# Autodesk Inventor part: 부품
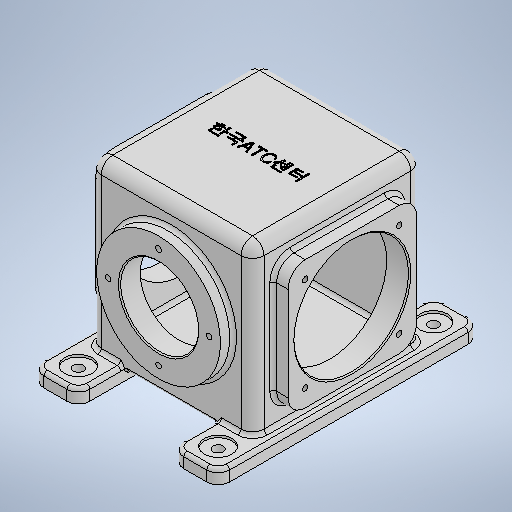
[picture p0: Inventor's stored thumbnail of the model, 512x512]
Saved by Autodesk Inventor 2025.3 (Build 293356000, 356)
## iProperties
Created: 2026-01
Part Number: 부품
Material: 일반
Document SubType Name: Modeling
Designer: pc6
Density: 1 g/cm^3
Appearance: 기본값
Author: pc6
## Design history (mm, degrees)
sketch "스케치1"
  geometry: L1 (71, -74)-(-71, -74); L2 (-71, -74)-(-71, 74); L3 (-71, 74)-(71, 74); L4 (71, 74)-(71, -74); 3 further points
  constraints: 8 end point, 2 midpoint, 2 parallel, 1 horizontal, 1 horizontal alignment, 1 perpendicular, 1 vertical alignment
  dimensions: "d0" = 142 distance between parallel lines of L4 L2; "d1" = 148 distance between parallel lines of L1 L3
extrude "돌출1" new body sketch "스케치1" stored distance "d2" = 148 (= d1); taper "d3" = 0 deg
sketch "스케치2"
  geometry: L1 (-10, 40)-(30, 40); L2 (30, 40)-(30, -188); L3 (30, -188)-(-10, -188); L4 (-10, -188)-(-10, 40); L5 (112, 40)-(152, 40); L6 (152, 40)-(152, -188); L7 (152, -188)-(112, -188); L8 (112, -188)-(112, 40); 5 further points
  constraints: 16 end point, 4 midpoint, 4 parallel, 2 horizontal, 2 horizontal alignment, 2 perpendicular
  dimensions: "d4" = 40 distance of L2.end L3.end; "d5" = 228 distance between parallel lines of L3 L1; "d6" = 40 distance of L6.end L7.end; "d7" = 228 distance between parallel lines of L7 L5; "d8" = 162 distance from line of point (152, -74) L4; "d9" = 81 distance of point (71, -74) point (-10, -74)
feature "쉘1" dims "d10" = 7
extrude "돌출2" join sketch "스케치2" distance "d11" = 8; taper "d12" = 0 deg; dims "d89" = 4, "d90" = 0
sketch "스케치5"
  geometry: L1 (130, -130)-(18, -130); L2 (18, -130)-(18, -18); L3 (18, -18)-(130, -18); L4 (130, -18)-(130, -130); L5 (130, -130)-(18, -18); L6 (18, -130)-(130, -18); L7 (188, -156)-(-40, -156) reference; 2 further points
  constraints: 12 end point, 2 midpoint, 2 parallel, 1 coincident, 1 horizontal, 1 perpendicular
  dimensions: "d19" = 112 distance of L2.end L3.end; "d20" = 112 distance of L1.end L2.end; "d21" = 82 distance from line of L7 point (74, -74)
extrude "돌출5" join sketch "스케치5" distance "d22" = 13; taper "d23" = 0 deg
sketch "스케치6"
  geometry: L1 (188, -156)-(-40, -156) reference; C1 r 50 at (74, -74); 1 further point
  constraints: 1 centre point, 1 coincident
  dimensions: "d24" = 100 diameter of C1; "d25" = 82 distance from line of L1 C1.centre
extrude "돌출6" cut sketch "스케치6" stored distance "d26" = 13; taper "d27" = 0 deg
sketch "스케치7"
  geometry: L1 (81, -82)-(41, -82) reference; C1 r 54 at (0, 0); C2 r 34 at (0, 0); 1 further point
  constraints: 2 centre point, 2 coincident
  dimensions: "d28" = 108 diameter of C1; "d29" = 82 distance from line of L1 C1.centre; "d30" = 68 diameter of C2
extrude "돌출7" join sketch "스케치7" distance "d31" = 11; taper "d32" = 0 deg
sketch "스케치8"
  geometry: L1 (81, -82)-(41, -82) reference; C1 r 34 at (0, 0); 2 further points
  constraints: 1 centre point, 1 coincident, 1 midpoint
  dimensions: "d33" = 68 diameter of C1; "d34" = 82 vertical distance of point (61, -82) C1.centre
extrude "돌출8" cut sketch "스케치8" stored distance "d35" = 11; taper "d36" = 0 deg
sketch "스케치9"
  geometry: 5 further points
  constraints: 1 horizontal alignment
  dimensions: "d44" = 82 distance of point (115, -33) point (33, -33); "d45" = 82 distance of point (33, -115) point (33, -33); "d46" = 82 distance of point (33, -115) point (115, -115); "d47" = 82 distance of point (115, -115) point (115, -33); "d48" = 41 horizontal distance of point (74, -74) point (33, -33); "d49" = 41 horizontal distance of point (115, -115) point (74, -74)
hole "구멍1" sketch "스케치9" at (115, -33), (33, -33), (33, -115), (115, -115) diameter "d37" = 4.917; stored, may be unused: countersink angle "d41" = 90 deg, drill point angle "d43" = 118 deg; dims "d38" = 12, "d39" = 4, "d40" = 2, "d42" = 12
sketch "스케치10" dims "d57" = 88
  geometry: L1 (81, -82)-(41, -82) reference; 4 further points
  constraints: 2 vertical alignment, 1 coincident, 1 midpoint, 2 other
  dimensions: "d58" = 82 vertical distance of point (61, -82) point (0, 0)
hole "구멍2" sketch "스케치10" at (0, 44) diameter "d50" = 4.917; stored, may be unused: countersink angle "d54" = 90 deg, drill point angle "d56" = 118 deg; dims "d51" = 12, "d52" = 4, "d53" = 2, "d55" = 12
fillet "모깎기1" dims "d62" = 10
fillet "모깎기2" dims "d63" = 10
fillet "모깎기5" dims "d66" = 15
fillet "모깎기6" dims "d67" = 3
chamfer "모따기1" distance "d68" = 1; stored, may be unused: second distance "d69" = 2, angle "d70" = 45 deg
fillet "모깎기7" dims "d71" = 3
sketch "스케치11"
  geometry: C1 r 12 at (10, -20); C2 r 12 at (132, -20); C3 r 12 at (132, 168); C4 r 12 at (10, 168); C5 r 4.5 at (10, -20); C6 r 4.5 at (132, -20); C7 r 4.5 at (132, 168); C8 r 4.5 at (10, 168); 1 further point
  constraints: 8 centre point, 4 coincident, 2 horizontal alignment, 1 vertical alignment
  dimensions: "d72" = 24 diameter of C1; "d73" = 24 diameter of C2; "d74" = 24 diameter of C3; "d75" = 24 diameter of C4; "d76" = 188 distance of C2.centre C3.centre; "d77" = 188 distance of C1.centre C4.centre; "d78" = 122 distance of C4.centre C3.centre; "d79" = 61 horizontal distance of C2.centre point (71, 74); "d80" = 94 vertical distance of C2.centre point (71, 74); "d83" = 9 diameter of C5; "d84" = 9 diameter of C6; "d85" = 9 diameter of C7; "d86" = 9 diameter of C8
extrude "돌출9" cut sketch "스케치11" distance "d81" = 2; taper "d82" = 0 deg
extrude "돌출10" cut sketch "스케치11" extent not by distance; stored distance "d87" = 0; taper "d88" = 0 deg
fillet "모깎기8" dims "d91" = 3
sketch "스케치12"
  geometry: 2 further points
  constraints: 1 other
feature "엠보싱1" sketch "스케치12" dims "d0" = 142, "d1" = 148, "d92" = 0.5, "d93" = 0
feature "ʭ耀ʯ耀ʱ耀ʳ耀ʵ耀ʷ耀ʹ耀ʻ耀" dims "d0" = 142, "d1" = 148, "d2" = 148 (= d1), "d3" = 0, "d4" = 40, "d5" = 228, "d6" = 40, "d7" = 228, "d8" = 162, "d9" = 81, "d10" = 7, "d11" = 8, "d12" = 0, "d19" = 112, "d20" = 112, "d21" = 82, "d22" = 13, "d23" = 0, "d24" = 100, "d25" = 82, "d26" = 13, "d27" = 0, "d28" = 108, "d29" = 82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
node "솔리드1"
mirror "미러1"
pattern_circular "원형 패턴1" dims angle "d60" = 360 deg
node "작업 평면1"
feature "A9D066F2-1C7D-4E18-AEED-F7BC21143FA4" dims "d37" = 4.917, "d38" = 12, "d39" = 4, "d40" = 2, "d41" = 90 deg, "d42" = 12, "d43" = 118 deg
